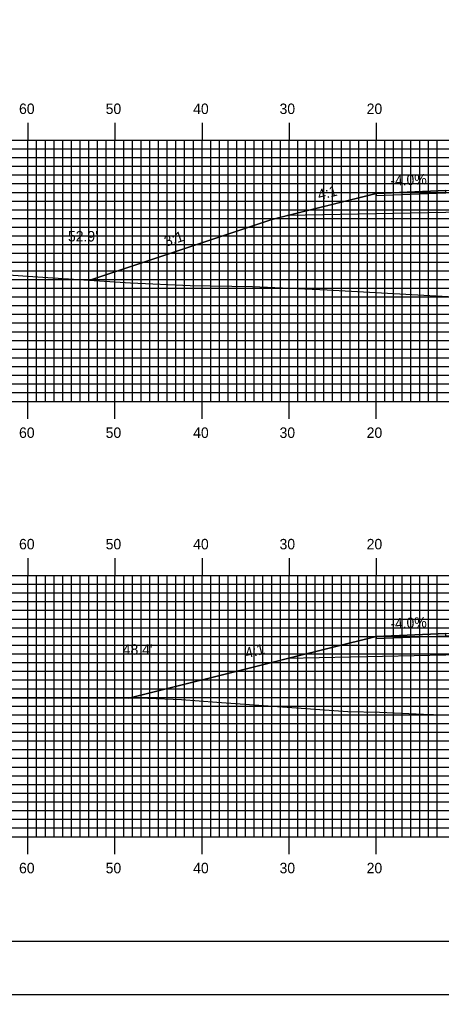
# Model space of a CAD drawing. Extents: x 1781073 to 1781416, y 442591 to 442811.
# Drawn here: x 1781177.9 to 1781226.4, y 442590.5 to 442702.5 of the extents above; entities that cross this region are included whole.
import ezdxf

# ---------------------------------------------------------------- set-up
doc = ezdxf.new("R2010")
doc.units = 0
for name, color, linetype in [('ANNOTATION', 7, 'Continuous'), ('BORDER', 7, 'Continuous'), ('D_Roadway_Centerline', 7, 'Continuous'), ('D_Roadway_Edge_Shoulder', 7, 'Continuous'), ('D_Roadway_SlopeLines', 7, 'Continuous'), ('D_Roadway_SubGrade', 7, 'Continuous'), ('D_Text_Standard', 7, 'Continuous'), ('H_V ANNOTATION', 7, 'Continuous'), ('MAJOR', 7, 'Continuous'), ('MINOR', 7, 'Continuous'), ('PLOT BOUNDARY', 7, 'Continuous'), ('S_Roadway_Centerline', 7, 'Continuous')]:
    doc.layers.add(name, color=color, linetype=linetype)

msp = doc.modelspace()

# ---------------------------------------------------------------- linework, layer by layer
at = {"layer": 'BORDER'}
msp.add_lwpolyline([(1781089.29, 442596.67), (1781409.29, 442596.67), (1781409.29, 442806.67), (1781089.29, 442806.67)], close=True, dxfattribs=at)
at = {"layer": 'D_Roadway_Centerline'}
for points in [[(1781185.99, 442672.58), (1781206.89, 442679.55), (1781208.72, 442680.01), (1781218.89, 442682.55), (1781226.89, 442682.87), (1781238.89, 442683.11), (1781250.89, 442682.87), (1781258.89, 442682.55), (1781269.07, 442680.01), (1781270.89, 442679.55), (1781305.63, 442667.98)], [(1781190.49, 442624.58), (1781206.89, 442628.68), (1781208.72, 442629.13), (1781218.89, 442631.68), (1781226.89, 442632), (1781238.89, 442632.24), (1781250.89, 442632), (1781258.89, 442631.68), (1781269.07, 442629.13), (1781270.89, 442628.68), (1781295.21, 442620.57)]]:
    msp.add_lwpolyline(points, dxfattribs=at)
at = {"layer": 'D_Roadway_Edge_Shoulder'}
for points in [[(1781226.89, 442682.87), (1781218.89, 442682.55), (1781218.89, 442682.3), (1781226.89, 442682.62)], [(1781226.89, 442632), (1781218.89, 442631.68), (1781218.89, 442631.43), (1781226.89, 442631.75)]]:
    msp.add_lwpolyline(points, close=True, dxfattribs=at)
at = {"layer": 'D_Roadway_SlopeLines'}
for points in [[(1781218.89, 442682.55), (1781206.89, 442679.55), (1781185.99, 442672.58)], [(1781218.89, 442631.68), (1781208.72, 442629.13), (1781206.89, 442628.68), (1781190.49, 442624.58)]]:
    msp.add_lwpolyline(points, dxfattribs=at)
at = {"layer": 'D_Roadway_SubGrade'}
for points in [[(1781226.89, 442680.37), (1781208.72, 442680.01), (1781218.89, 442682.55), (1781218.89, 442682.3), (1781226.89, 442682.62), (1781238.89, 442682.86), (1781250.89, 442682.62), (1781258.89, 442682.3), (1781258.89, 442682.55), (1781269.07, 442680.01), (1781250.89, 442680.37), (1781238.89, 442680.61)], [(1781226.89, 442629.5), (1781208.72, 442629.13), (1781218.89, 442631.68), (1781218.89, 442631.43), (1781226.89, 442631.75), (1781238.89, 442631.99), (1781250.89, 442631.75), (1781258.89, 442631.43), (1781258.89, 442631.68), (1781269.07, 442629.13), (1781250.89, 442629.5), (1781238.89, 442629.74)]]:
    msp.add_lwpolyline(points, close=True, dxfattribs=at)
at = {"layer": 'MAJOR'}
for p, q in [((1781178.89, 442690.67), (1781178.89, 442688.67)), ((1781188.89, 442690.67), (1781188.89, 442688.67)), ((1781198.89, 442690.67), (1781198.89, 442688.67)), ((1781208.89, 442690.67), (1781208.89, 442688.67)), ((1781218.89, 442690.67), (1781218.89, 442688.67)), ((1781098.89, 442688.67), (1781378.89, 442688.67)), ((1781098.89, 442688.67), (1781378.89, 442688.67)), ((1781178.89, 442658.67), (1781178.89, 442688.67)), ((1781188.89, 442658.67), (1781188.89, 442688.67)), ((1781198.89, 442658.67), (1781198.89, 442688.67)), ((1781208.89, 442658.67), (1781208.89, 442688.67)), ((1781218.89, 442658.67), (1781218.89, 442688.67)), ((1781098.89, 442683.67), (1781378.89, 442683.67)), ((1781098.89, 442678.67), (1781378.89, 442678.67)), ((1781098.89, 442673.67), (1781378.89, 442673.67)), ((1781098.89, 442668.67), (1781378.89, 442668.67)), ((1781098.89, 442663.67), (1781378.89, 442663.67)), ((1781098.89, 442658.67), (1781378.89, 442658.67)), ((1781098.89, 442658.67), (1781378.89, 442658.67)), ((1781178.89, 442656.66), (1781178.89, 442658.67)), ((1781188.89, 442656.66), (1781188.89, 442658.67)), ((1781198.89, 442656.66), (1781198.89, 442658.67)), ((1781208.89, 442656.66), (1781208.89, 442658.67)), ((1781218.89, 442656.66), (1781218.89, 442658.67)), ((1781178.89, 442640.67), (1781178.89, 442638.67)), ((1781188.89, 442640.67), (1781188.89, 442638.67)), ((1781198.89, 442640.67), (1781198.89, 442638.67)), ((1781208.89, 442640.67), (1781208.89, 442638.67)), ((1781218.89, 442640.67), (1781218.89, 442638.67)), ((1781098.89, 442638.67), (1781378.89, 442638.67)), ((1781098.89, 442638.67), (1781378.89, 442638.67)), ((1781178.89, 442608.67), (1781178.89, 442638.67)), ((1781188.89, 442608.67), (1781188.89, 442638.67)), ((1781198.89, 442608.67), (1781198.89, 442638.67)), ((1781208.89, 442608.67), (1781208.89, 442638.67)), ((1781218.89, 442608.67), (1781218.89, 442638.67)), ((1781098.89, 442633.67), (1781378.89, 442633.67)), ((1781098.89, 442628.67), (1781378.89, 442628.67)), ((1781098.89, 442623.67), (1781378.89, 442623.67)), ((1781098.89, 442618.67), (1781378.89, 442618.67)), ((1781098.89, 442613.67), (1781378.89, 442613.67)), ((1781098.89, 442608.67), (1781378.89, 442608.67)), ((1781098.89, 442608.67), (1781378.89, 442608.67)), ((1781178.89, 442606.66), (1781178.89, 442608.67)), ((1781188.89, 442606.66), (1781188.89, 442608.67)), ((1781198.89, 442606.66), (1781198.89, 442608.67)), ((1781208.89, 442606.66), (1781208.89, 442608.67)), ((1781218.89, 442606.66), (1781218.89, 442608.67))]:
    msp.add_line(p, q, dxfattribs=at)
at = {"layer": 'MINOR'}
for p, q in [((1781179.89, 442658.67), (1781179.89, 442688.67)), ((1781180.89, 442658.67), (1781180.89, 442688.67)), ((1781181.89, 442658.67), (1781181.89, 442688.67)), ((1781182.89, 442658.67), (1781182.89, 442688.67)), ((1781183.89, 442658.67), (1781183.89, 442688.67)), ((1781184.89, 442658.67), (1781184.89, 442688.67)), ((1781185.89, 442658.67), (1781185.89, 442688.67)), ((1781186.89, 442658.67), (1781186.89, 442688.67)), ((1781187.89, 442658.67), (1781187.89, 442688.67)), ((1781189.89, 442658.67), (1781189.89, 442688.67)), ((1781190.89, 442658.67), (1781190.89, 442688.67)), ((1781191.89, 442658.67), (1781191.89, 442688.67)), ((1781192.89, 442658.67), (1781192.89, 442688.67)), ((1781193.89, 442658.67), (1781193.89, 442688.67)), ((1781194.89, 442658.67), (1781194.89, 442688.67)), ((1781195.89, 442658.67), (1781195.89, 442688.67)), ((1781196.89, 442658.67), (1781196.89, 442688.67)), ((1781197.89, 442658.67), (1781197.89, 442688.67)), ((1781199.89, 442658.67), (1781199.89, 442688.67)), ((1781200.89, 442658.67), (1781200.89, 442688.67)), ((1781201.89, 442658.67), (1781201.89, 442688.67)), ((1781202.89, 442658.67), (1781202.89, 442688.67)), ((1781203.89, 442658.67), (1781203.89, 442688.67)), ((1781204.89, 442658.67), (1781204.89, 442688.67)), ((1781205.89, 442658.67), (1781205.89, 442688.67)), ((1781206.89, 442658.67), (1781206.89, 442688.67)), ((1781207.89, 442658.67), (1781207.89, 442688.67)), ((1781209.89, 442658.67), (1781209.89, 442688.67)), ((1781210.89, 442658.67), (1781210.89, 442688.67)), ((1781211.89, 442658.67), (1781211.89, 442688.67)), ((1781212.89, 442658.67), (1781212.89, 442688.67)), ((1781213.89, 442658.67), (1781213.89, 442688.67)), ((1781214.89, 442658.67), (1781214.89, 442688.67)), ((1781215.89, 442658.67), (1781215.89, 442688.67)), ((1781216.89, 442658.67), (1781216.89, 442688.67)), ((1781217.89, 442658.67), (1781217.89, 442688.67)), ((1781219.89, 442658.67), (1781219.89, 442688.67)), ((1781220.89, 442658.67), (1781220.89, 442688.67)), ((1781221.89, 442658.67), (1781221.89, 442688.67)), ((1781222.89, 442658.67), (1781222.89, 442688.67)), ((1781223.89, 442658.67), (1781223.89, 442688.67)), ((1781224.89, 442658.67), (1781224.89, 442688.67)), ((1781225.89, 442658.67), (1781225.89, 442688.67)), ((1781098.89, 442687.67), (1781378.89, 442687.67)), ((1781098.89, 442686.67), (1781378.89, 442686.67)), ((1781098.89, 442685.67), (1781378.89, 442685.67)), ((1781098.89, 442684.67), (1781378.89, 442684.67)), ((1781098.89, 442682.67), (1781378.89, 442682.67)), ((1781098.89, 442681.67), (1781378.89, 442681.67)), ((1781098.89, 442680.67), (1781378.89, 442680.67)), ((1781098.89, 442679.67), (1781378.89, 442679.67)), ((1781098.89, 442677.67), (1781378.89, 442677.67)), ((1781098.89, 442676.67), (1781378.89, 442676.67)), ((1781098.89, 442675.67), (1781378.89, 442675.67)), ((1781098.89, 442674.67), (1781378.89, 442674.67)), ((1781098.89, 442672.67), (1781378.89, 442672.67)), ((1781098.89, 442671.67), (1781378.89, 442671.67)), ((1781098.89, 442670.67), (1781378.89, 442670.67)), ((1781098.89, 442669.67), (1781378.89, 442669.67)), ((1781098.89, 442667.67), (1781378.89, 442667.67)), ((1781098.89, 442666.67), (1781378.89, 442666.67)), ((1781098.89, 442665.67), (1781378.89, 442665.67)), ((1781098.89, 442664.67), (1781378.89, 442664.67)), ((1781098.89, 442662.67), (1781378.89, 442662.67)), ((1781098.89, 442661.67), (1781378.89, 442661.67)), ((1781098.89, 442660.67), (1781378.89, 442660.67)), ((1781098.89, 442659.67), (1781378.89, 442659.67)), ((1781179.89, 442608.67), (1781179.89, 442638.67)), ((1781180.89, 442608.67), (1781180.89, 442638.67)), ((1781181.89, 442608.67), (1781181.89, 442638.67)), ((1781182.89, 442608.67), (1781182.89, 442638.67)), ((1781183.89, 442608.67), (1781183.89, 442638.67)), ((1781184.89, 442608.67), (1781184.89, 442638.67)), ((1781185.89, 442608.67), (1781185.89, 442638.67)), ((1781186.89, 442608.67), (1781186.89, 442638.67)), ((1781187.89, 442608.67), (1781187.89, 442638.67)), ((1781189.89, 442608.67), (1781189.89, 442638.67)), ((1781190.89, 442608.67), (1781190.89, 442638.67)), ((1781191.89, 442608.67), (1781191.89, 442638.67)), ((1781192.89, 442608.67), (1781192.89, 442638.67)), ((1781193.89, 442608.67), (1781193.89, 442638.67)), ((1781194.89, 442608.67), (1781194.89, 442638.67)), ((1781195.89, 442608.67), (1781195.89, 442638.67)), ((1781196.89, 442608.67), (1781196.89, 442638.67)), ((1781197.89, 442608.67), (1781197.89, 442638.67)), ((1781199.89, 442608.67), (1781199.89, 442638.67)), ((1781200.89, 442608.67), (1781200.89, 442638.67)), ((1781201.89, 442608.67), (1781201.89, 442638.67)), ((1781202.89, 442608.67), (1781202.89, 442638.67)), ((1781203.89, 442608.67), (1781203.89, 442638.67)), ((1781204.89, 442608.67), (1781204.89, 442638.67)), ((1781205.89, 442608.67), (1781205.89, 442638.67)), ((1781206.89, 442608.67), (1781206.89, 442638.67)), ((1781207.89, 442608.67), (1781207.89, 442638.67)), ((1781209.89, 442608.67), (1781209.89, 442638.67)), ((1781210.89, 442608.67), (1781210.89, 442638.67)), ((1781211.89, 442608.67), (1781211.89, 442638.67)), ((1781212.89, 442608.67), (1781212.89, 442638.67)), ((1781213.89, 442608.67), (1781213.89, 442638.67)), ((1781214.89, 442608.67), (1781214.89, 442638.67)), ((1781215.89, 442608.67), (1781215.89, 442638.67)), ((1781216.89, 442608.67), (1781216.89, 442638.67)), ((1781217.89, 442608.67), (1781217.89, 442638.67)), ((1781219.89, 442608.67), (1781219.89, 442638.67)), ((1781220.89, 442608.67), (1781220.89, 442638.67)), ((1781221.89, 442608.67), (1781221.89, 442638.67)), ((1781222.89, 442608.67), (1781222.89, 442638.67)), ((1781223.89, 442608.67), (1781223.89, 442638.67)), ((1781224.89, 442608.67), (1781224.89, 442638.67)), ((1781225.89, 442608.67), (1781225.89, 442638.67)), ((1781098.89, 442637.67), (1781378.89, 442637.67)), ((1781098.89, 442636.67), (1781378.89, 442636.67)), ((1781098.89, 442635.67), (1781378.89, 442635.67)), ((1781098.89, 442634.67), (1781378.89, 442634.67)), ((1781098.89, 442632.67), (1781378.89, 442632.67)), ((1781098.89, 442631.67), (1781378.89, 442631.67)), ((1781098.89, 442630.67), (1781378.89, 442630.67)), ((1781098.89, 442629.67), (1781378.89, 442629.67)), ((1781098.89, 442627.67), (1781378.89, 442627.67)), ((1781098.89, 442626.67), (1781378.89, 442626.67)), ((1781098.89, 442625.67), (1781378.89, 442625.67)), ((1781098.89, 442624.67), (1781378.89, 442624.67)), ((1781098.89, 442622.67), (1781378.89, 442622.67)), ((1781098.89, 442621.67), (1781378.89, 442621.67)), ((1781098.89, 442620.67), (1781378.89, 442620.67)), ((1781098.89, 442619.67), (1781378.89, 442619.67)), ((1781098.89, 442617.67), (1781378.89, 442617.67)), ((1781098.89, 442616.67), (1781378.89, 442616.67)), ((1781098.89, 442615.67), (1781378.89, 442615.67)), ((1781098.89, 442614.67), (1781378.89, 442614.67)), ((1781098.89, 442612.67), (1781378.89, 442612.67)), ((1781098.89, 442611.67), (1781378.89, 442611.67)), ((1781098.89, 442610.67), (1781378.89, 442610.67)), ((1781098.89, 442609.67), (1781378.89, 442609.67))]:
    msp.add_line(p, q, dxfattribs=at)
at = {"layer": 'PLOT BOUNDARY'}
msp.add_lwpolyline([(1781073.11, 442590.55), (1781413.11, 442590.55), (1781413.11, 442810.55), (1781073.11, 442810.55)], close=True, dxfattribs=at)
at = {"layer": 'S_Roadway_Centerline'}
for points in [[(1781174.3, 442673.36), (1781181.76, 442672.85), (1781190.68, 442672.29), (1781197.53, 442671.96), (1781204.7, 442671.85), (1781213.28, 442671.48), (1781228.52, 442670.62), (1781234.75, 442670.42), (1781252.07, 442669.85), (1781254.41, 442669.78), (1781257.06, 442669.67), (1781266.95, 442669.1), (1781276.5, 442668.37), (1781281.17, 442668.06), (1781289.95, 442668.04), (1781299.54, 442668.01)], [(1781172.63, 442624.6), (1781192.65, 442624.57), (1781196.54, 442624.41), (1781200.59, 442624.11), (1781215.65, 442623.03), (1781219.28, 442622.97), (1781224.31, 442622.75), (1781242.58, 442622.12), (1781246.18, 442622.1), (1781253.57, 442622.22), (1781270.57, 442621.33), (1781276.87, 442620.98), (1781283.97, 442620.7), (1781288.82, 442620.61), (1781294.69, 442620.58), (1781301.58, 442620.54)]]:
    msp.add_lwpolyline(points, dxfattribs=at)

# ---------------------------------------------------------------- texts
at = {"layer": 'ANNOTATION'}
for s, rotation, p in [('-4.0%', 2.2906, (1781220.53, 442683.42)), ('4:1', 14.0362, (1781212.34, 442681.78)), ('3:1', 18.4348, (1781194.78, 442676.42)), ('-4.0%', 2.2906, (1781220.53, 442632.54)), ('4:1', 14.0362, (1781204.01, 442629.15))]:
    msp.add_text(s, height=1.2, rotation=rotation, dxfattribs=at).set_placement(p)
at = {"layer": 'D_Text_Standard'}
for s, p in [("52.9'", (1781183.49, 442677.03)), ("48.4'", (1781189.78, 442629.57))]:
    msp.add_text(s, height=1.2, dxfattribs=at).set_placement(p)
at = {"layer": 'H_V ANNOTATION'}
for s, p in [('60', (1781177.87, 442691.67)), ('50', (1781187.82, 442691.67)), ('40', (1781197.87, 442691.67)), ('30', (1781207.79, 442691.67)), ('20', (1781217.8, 442691.67)), ('60', (1781177.87, 442654.47)), ('50', (1781187.82, 442654.47)), ('40', (1781197.87, 442654.47)), ('30', (1781207.79, 442654.47)), ('20', (1781217.8, 442654.47)), ('60', (1781177.87, 442641.67)), ('50', (1781187.82, 442641.67)), ('40', (1781197.87, 442641.67)), ('30', (1781207.79, 442641.67)), ('20', (1781217.8, 442641.67)), ('60', (1781177.87, 442604.47)), ('50', (1781187.82, 442604.47)), ('40', (1781197.87, 442604.47)), ('30', (1781207.79, 442604.47)), ('20', (1781217.8, 442604.47))]:
    msp.add_text(s, height=1.2, dxfattribs=at).set_placement(p)

doc.saveas('drawing.dxf')
